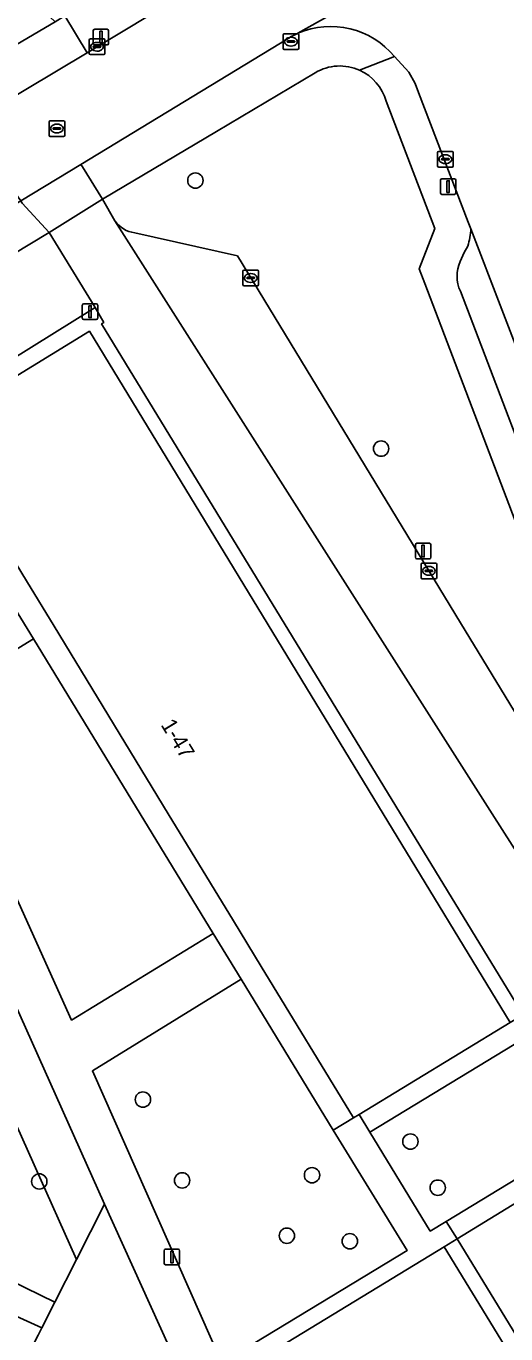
# Model space of a CAD drawing. Extents: x 159960 to 160866, y 382700 to 383354.
# Drawn here: x 160323.3 to 160353.9, y 382966.8 to 383050.3 of the extents above; entities that cross this region are included whole.
import ezdxf

# ---------------------------------------------------------------- set-up
doc = ezdxf.new("R2010")
doc.units = 0
for name, color, linetype in [('IMGEO_Boom', 7, 'Continuous'), ('IMGEO_Erf', 7, 'Continuous'), ('IMGEO_Groenvoorziening', 7, 'Continuous'), ('IMGEO_Kolk', 7, 'Continuous'), ('IMGEO_Lichtmast', 7, 'Continuous'), ('IMGEO_Pand', 7, 'Continuous'), ('IMGEO_Pand_nummerreeks', 7, 'Continuous'), ('IMGEO_Parkeervlak_open', 7, 'Continuous'), ('IMGEO_Rijbaan_lokaal_open', 7, 'Continuous'), ('IMGEO_Rioolput', 7, 'Continuous'), ('IMGEO_Voetpad_open', 7, 'Continuous')]:
    doc.layers.add(name, color=color, linetype=linetype)

msp = doc.modelspace()

# ---------------------------------------------------------------- linework, layer by layer
at = {"layer": 'IMGEO_Boom'}
for centre in [(160334.084, 383040.41), (160345.925, 383023.303), (160330.742, 382981.762), (160347.793, 382979.083), (160324.135, 382976.538), (160333.242, 382976.606), (160341.521, 382976.938), (160349.536, 382976.141), (160339.918, 382973.076), (160343.933, 382972.722)]:
    msp.add_circle(centre, 0.489, dxfattribs=at)
at = {"layer": 'IMGEO_Erf'}
msp.add_lwpolyline([(160338.283, 382990.248), (160336.511, 382993.16), (160332.352, 383000), (160325.073, 383011.971), (160323.309, 383014.872), (160317.351, 383024.674), (160327.335, 383030.788), (160346.052, 383000), (160354.153, 382986.675), (160354.977, 382987.18), (160328.108, 383031.263), (160328.241, 383031.36), (160327.687, 383032.3), (160315.507, 383024.71), (160316.015, 383023.874), (160321.983, 383014.084), (160323.762, 383011.165), (160330.567, 383000), (160335.219, 382992.368), (160336.996, 382989.452), (160342.867, 382979.821), (160344.157, 382980.593)], close=True, dxfattribs=at)
msp.add_lwpolyline([(160377.609, 382928.902), (160350.766, 382972.869), (160349.953, 382972.37), (160376.799, 382928.407)], dxfattribs=at)
at = {"layer": 'IMGEO_Groenvoorziening'}
for points in [[(160341.728, 383047.288), (160335.442, 383043.546), (160328.163, 383039.213), (160328.956, 383037.843)], [(160350.986, 383027.855), (160348.704, 383033.84), (160348.346, 383034.778), (160349.347, 383037.342), (160346.241, 383045.476)], [(160316.015, 383023.874), (160315.507, 383024.71), (160327.687, 383032.3), (160324.759, 383037.085), (160315.53, 383031.527)], [(160330.218, 383037.075), (160336.761, 383035.598), (160350.986, 383012.188), (160358.396, 383000), (160363.112, 382992.243), (160362.536, 382990.002), (160358.735, 382991.005), (160363.982, 382982.064)], [(160367.124, 382980.721), (160368.513, 382981.603), (160361.585, 383000), (160361.047, 383001.415), (160350.986, 383027.855)], [(160312.984, 383001.767), (160326.499, 382971.558), (160328.285, 382975.093), (160317.112, 383000.067)], [(160352.331, 382917.287), (160348.225, 382919.407), (160339.351, 382923.988), (160327.271, 382930.315), (160324.735, 382931.639), (160310.176, 382939.24), (160309.738, 382939.468), (160324.059, 382966.726), (160324.298, 382967.199), (160317.027, 382970.5)]]:
    msp.add_lwpolyline(points, dxfattribs=at)
for points in [[(160330.567, 383000), (160323.762, 383011.165), (160317.074, 383007.055), (160326.198, 382986.837), (160335.219, 382992.368)], [(160312.984, 383001.767), (160312.699, 383001.659), (160310.309, 383000.605), (160310.574, 383000), (160321.333, 382975.447), (160319.46, 382971.602), (160325.126, 382968.84), (160326.499, 382971.558)], [(160342.867, 382979.821), (160336.996, 382989.452), (160327.521, 382983.59), (160335.771, 382964.957), (160347.584, 382972.132)], [(160350.081, 382973.991), (160357.379, 382978.431), (160356.163, 382980.43), (160357.034, 382980.96), (160354.404, 382985.283), (160345.212, 382979.69), (160349.058, 382973.368)]]:
    msp.add_lwpolyline(points, close=True, dxfattribs=at)
for centre, radius, start, end in [((160343.295, 383044.661), 3.059, 65.61805, 120.81337), ((160343.297, 383044.666), 3.053, 15.37638, 65.6104), ((160330.423, 383038.833), 1.769, 214.00285, 263.35129)]:
    msp.add_arc(centre, radius, start, end, dxfattribs=at)
at = {"layer": 'IMGEO_Kolk'}
for p, q in [((160339.678, 383048.847), (160339.678, 383049.699)), ((160339.753, 383049.773), (160340.605, 383049.773)), ((160340.679, 383049.699), (160340.679, 383048.847)), ((160327.315, 383048.52), (160327.315, 383049.372)), ((160327.39, 383049.446), (160328.242, 383049.446)), ((160327.574, 383048.94), (160327.574, 383048.952)), ((160328.012, 383048.903), (160327.614, 383048.903)), ((160327.617, 383048.989), (160328.015, 383048.989)), ((160327.803, 383049.226), (160327.828, 383049.226)), ((160328.058, 383048.952), (160328.058, 383048.94)), ((160328.316, 383049.372), (160328.316, 383048.52)), ((160340.605, 383048.773), (160339.753, 383048.773)), ((160339.937, 383049.267), (160339.937, 383049.279)), ((160340.375, 383049.23), (160339.977, 383049.23)), ((160339.98, 383049.316), (160340.378, 383049.316)), ((160340.189, 383048.993), (160340.164, 383048.993)), ((160340.166, 383049.553), (160340.191, 383049.553)), ((160340.421, 383049.279), (160340.421, 383049.267)), ((160328.242, 383048.446), (160327.39, 383048.446)), ((160327.826, 383048.666), (160327.801, 383048.666)), ((160349.523, 383041.346), (160349.523, 383042.198)), ((160349.598, 383042.272), (160350.45, 383042.272)), ((160350.524, 383042.198), (160350.524, 383041.346)), ((160350.45, 383041.272), (160349.598, 383041.272)), ((160349.782, 383041.766), (160349.782, 383041.778)), ((160350.22, 383041.729), (160349.822, 383041.729)), ((160349.825, 383041.815), (160350.223, 383041.815)), ((160350.034, 383041.492), (160350.009, 383041.492)), ((160350.011, 383042.052), (160350.036, 383042.052)), ((160350.266, 383041.778), (160350.266, 383041.766)), ((160337.115, 383033.767), (160337.115, 383034.619)), ((160337.19, 383034.693), (160338.042, 383034.693)), ((160338.116, 383034.619), (160338.116, 383033.767)), ((160337.374, 383034.187), (160337.374, 383034.199)), ((160337.812, 383034.15), (160337.414, 383034.15)), ((160337.417, 383034.236), (160337.815, 383034.236)), ((160337.626, 383033.913), (160337.601, 383033.913)), ((160337.603, 383034.473), (160337.628, 383034.473)), ((160337.858, 383034.199), (160337.858, 383034.187)), ((160338.042, 383033.693), (160337.19, 383033.693)), ((160348.473, 383015.075), (160348.473, 383015.927)), ((160348.548, 383016.001), (160349.4, 383016.001)), ((160348.732, 383015.495), (160348.732, 383015.507)), ((160349.17, 383015.458), (160348.772, 383015.458)), ((160348.775, 383015.544), (160349.173, 383015.544)), ((160348.961, 383015.781), (160348.986, 383015.781)), ((160349.216, 383015.507), (160349.216, 383015.495)), ((160349.474, 383015.927), (160349.474, 383015.075)), ((160349.4, 383015.001), (160348.548, 383015.001)), ((160348.984, 383015.221), (160348.959, 383015.221))]:
    msp.add_line(p, q, dxfattribs=at)
for points in [[(160339.678, 383048.847), (160339.678, 383049.699)], [(160339.753, 383049.773), (160340.605, 383049.773)], [(160340.679, 383049.699), (160340.679, 383048.847)], [(160327.315, 383048.52), (160327.315, 383049.372)], [(160327.39, 383049.446), (160328.242, 383049.446)], [(160328.316, 383049.372), (160328.316, 383048.52)], [(160340.605, 383048.773), (160339.753, 383048.773)], [(160328.242, 383048.446), (160327.39, 383048.446)], [(160349.523, 383041.346), (160349.523, 383042.198)], [(160349.598, 383042.272), (160350.45, 383042.272)], [(160350.524, 383042.198), (160350.524, 383041.346)], [(160350.45, 383041.272), (160349.598, 383041.272)], [(160337.115, 383033.767), (160337.115, 383034.619)], [(160337.19, 383034.693), (160338.042, 383034.693)], [(160338.116, 383034.619), (160338.116, 383033.767)], [(160338.042, 383033.693), (160337.19, 383033.693)], [(160348.473, 383015.075), (160348.473, 383015.927)], [(160348.548, 383016.001), (160349.4, 383016.001)], [(160349.474, 383015.927), (160349.474, 383015.075)], [(160349.4, 383015.001), (160348.548, 383015.001)]]:
    msp.add_lwpolyline(points, dxfattribs=at)
for centre, radius, start, end in [((160339.755, 383049.697), 0.0765, 91.55205, 178.44795), ((160339.755, 383049.697), 0.0765, 91.55205, 178.44795), ((160340.603, 383049.697), 0.0765, 1.55205, 88.44795), ((160340.603, 383049.697), 0.0765, 1.55205, 88.44795), ((160327.392, 383049.37), 0.0765, 91.55205, 178.44795), ((160327.392, 383049.37), 0.0765, 91.55205, 178.44795), ((160327.614, 383048.949), 0.0403, 85.87752, 175.75265), ((160327.611, 383048.939), 0.0366, 178.93798, 274.71019), ((160328.015, 383048.946), 0.043, 264.86636, 352.45326), ((160328.019, 383048.951), 0.0386, 1.73085, 96.63898), ((160328.24, 383049.37), 0.0765, 1.55205, 88.44795), ((160328.24, 383049.37), 0.0765, 1.55205, 88.44795), ((160339.755, 383048.849), 0.0765, 181.55205, 268.44795), ((160339.755, 383048.849), 0.0765, 181.55205, 268.44795), ((160339.977, 383049.276), 0.0403, 85.87752, 175.75265), ((160339.974, 383049.266), 0.0366, 178.93798, 274.71019), ((160340.378, 383049.273), 0.043, 264.86636, 352.45326), ((160340.382, 383049.278), 0.0386, 1.73085, 96.63898), ((160340.603, 383048.849), 0.0765, 271.55205, 358.44795), ((160340.603, 383048.849), 0.0765, 271.55205, 358.44795), ((160327.392, 383048.522), 0.0765, 181.55205, 268.44795), ((160327.392, 383048.522), 0.0765, 181.55205, 268.44795), ((160328.24, 383048.522), 0.0765, 271.55205, 358.44795), ((160328.24, 383048.522), 0.0765, 271.55205, 358.44795), ((160349.6, 383042.196), 0.0765, 91.55205, 178.44795), ((160349.6, 383042.196), 0.0765, 91.55205, 178.44795), ((160350.448, 383042.196), 0.0765, 1.55205, 88.44795), ((160350.448, 383042.196), 0.0765, 1.55205, 88.44795), ((160349.6, 383041.348), 0.0765, 181.55205, 268.44795), ((160349.6, 383041.348), 0.0765, 181.55205, 268.44795), ((160349.822, 383041.775), 0.0403, 85.87752, 175.75265), ((160349.819, 383041.765), 0.0366, 178.93798, 274.71019), ((160350.223, 383041.772), 0.043, 264.86636, 352.45326), ((160350.227, 383041.777), 0.0386, 1.73085, 96.63898), ((160350.448, 383041.348), 0.0765, 271.55205, 358.44795), ((160350.448, 383041.348), 0.0765, 271.55205, 358.44795), ((160337.192, 383034.617), 0.0765, 91.55205, 178.44795), ((160337.192, 383034.617), 0.0765, 91.55205, 178.44795), ((160338.04, 383034.617), 0.0765, 1.55205, 88.44795), ((160338.04, 383034.617), 0.0765, 1.55205, 88.44795), ((160337.192, 383033.769), 0.0765, 181.55205, 268.44795), ((160337.192, 383033.769), 0.0765, 181.55205, 268.44795), ((160337.414, 383034.196), 0.0403, 85.87752, 175.75265), ((160337.411, 383034.186), 0.0366, 178.93798, 274.71019), ((160337.815, 383034.193), 0.043, 264.86636, 352.45326), ((160337.819, 383034.198), 0.0386, 1.73085, 96.63898), ((160338.04, 383033.769), 0.0765, 271.55205, 358.44795), ((160338.04, 383033.769), 0.0765, 271.55205, 358.44795), ((160348.55, 383015.925), 0.0765, 91.55205, 178.44795), ((160348.55, 383015.925), 0.0765, 91.55205, 178.44795), ((160348.772, 383015.504), 0.0403, 85.87752, 175.75265), ((160348.769, 383015.494), 0.0366, 178.93798, 274.71019), ((160349.173, 383015.501), 0.043, 264.86636, 352.45326), ((160349.177, 383015.506), 0.0386, 1.73085, 96.63898), ((160349.398, 383015.925), 0.0765, 1.55205, 88.44795), ((160349.398, 383015.925), 0.0765, 1.55205, 88.44795), ((160348.55, 383015.077), 0.0765, 181.55205, 268.44795), ((160348.55, 383015.077), 0.0765, 181.55205, 268.44795), ((160349.398, 383015.077), 0.0765, 271.55205, 358.44795), ((160349.398, 383015.077), 0.0765, 271.55205, 358.44795)]:
    msp.add_arc(centre, radius, start, end, dxfattribs=at)
for centre, major_axis, ratio, start_param, end_param in [((160327.802, 383048.946), (-0.387, 0.002), 0.722429, 4.712389, 7.853982), ((160327.827, 383048.946), (-0.39, 0.002), 0.717154, 1.570796, 4.712389), ((160340.165, 383049.273), (-0.387, 0.002), 0.722429, 4.712389, 7.853982), ((160340.19, 383049.273), (-0.39, 0.002), 0.717154, 1.570796, 4.712389), ((160350.01, 383041.772), (-0.387, 0.002), 0.722429, 4.712389, 7.853982), ((160350.035, 383041.772), (-0.39, 0.002), 0.717154, 1.570796, 4.712389), ((160337.602, 383034.193), (-0.387, 0.002), 0.722429, 4.712389, 7.853982), ((160337.627, 383034.193), (-0.39, 0.002), 0.717154, 1.570796, 4.712389), ((160348.96, 383015.501), (-0.387, 0.002), 0.722429, 4.712389, 7.853982), ((160348.985, 383015.501), (-0.39, 0.002), 0.717154, 1.570796, 4.712389)]:
    msp.add_ellipse(centre, major_axis=major_axis, ratio=ratio, start_param=start_param, end_param=end_param, dxfattribs=at)
at = {"layer": 'IMGEO_Lichtmast'}
for p, q in [((160327.566, 383049.164), (160327.566, 383049.964)), ((160327.566, 383049.964), (160327.566, 383049.164)), ((160327.666, 383050.064), (160328.456, 383050.064)), ((160328.456, 383050.064), (160327.666, 383050.064)), ((160328.556, 383049.964), (160328.556, 383049.164)), ((160328.556, 383049.164), (160328.556, 383049.964)), ((160328.456, 383049.064), (160327.666, 383049.064)), ((160327.666, 383049.064), (160328.456, 383049.064)), ((160349.705, 383039.624), (160349.705, 383040.424)), ((160349.705, 383040.424), (160349.705, 383039.624)), ((160349.805, 383040.524), (160350.595, 383040.524)), ((160350.595, 383040.524), (160349.805, 383040.524)), ((160350.695, 383040.424), (160350.695, 383039.624)), ((160350.695, 383039.624), (160350.695, 383040.424)), ((160350.595, 383039.524), (160349.805, 383039.524)), ((160349.805, 383039.524), (160350.595, 383039.524)), ((160326.873, 383031.644), (160326.873, 383032.444)), ((160326.873, 383032.444), (160326.873, 383031.644)), ((160326.973, 383032.544), (160327.763, 383032.544)), ((160327.763, 383032.544), (160326.973, 383032.544)), ((160327.863, 383032.444), (160327.863, 383031.644)), ((160327.863, 383031.644), (160327.863, 383032.444)), ((160327.763, 383031.544), (160326.973, 383031.544)), ((160326.973, 383031.544), (160327.763, 383031.544)), ((160348.112, 383016.366), (160348.112, 383017.166)), ((160348.112, 383017.166), (160348.112, 383016.366)), ((160348.212, 383017.266), (160349.002, 383017.266)), ((160349.002, 383017.266), (160348.212, 383017.266)), ((160349.102, 383017.166), (160349.102, 383016.366)), ((160349.102, 383016.366), (160349.102, 383017.166)), ((160349.002, 383016.266), (160348.212, 383016.266)), ((160348.212, 383016.266), (160349.002, 383016.266)), ((160332.091, 382971.321), (160332.091, 382972.121)), ((160332.091, 382972.121), (160332.091, 382971.321)), ((160332.191, 382972.221), (160332.981, 382972.221)), ((160332.981, 382972.221), (160332.191, 382972.221)), ((160333.081, 382972.121), (160333.081, 382971.321)), ((160333.081, 382971.321), (160333.081, 382972.121)), ((160332.981, 382971.221), (160332.191, 382971.221)), ((160332.191, 382971.221), (160332.981, 382971.221))]:
    msp.add_line(p, q, dxfattribs=at)
for points in [[(160327.986, 383049.939), (160328.136, 383049.939), (160328.136, 383049.189), (160327.986, 383049.189), (160327.986, 383049.939)], [(160350.125, 383040.399), (160350.275, 383040.399), (160350.275, 383039.649), (160350.125, 383039.649), (160350.125, 383040.399)], [(160327.293, 383032.419), (160327.443, 383032.419), (160327.443, 383031.669), (160327.293, 383031.669), (160327.293, 383032.419)], [(160348.532, 383017.141), (160348.682, 383017.141), (160348.682, 383016.391), (160348.532, 383016.391), (160348.532, 383017.141)], [(160332.511, 382972.096), (160332.661, 382972.096), (160332.661, 382971.346), (160332.511, 382971.346), (160332.511, 382972.096)]]:
    msp.add_lwpolyline(points, dxfattribs=at)
for centre, start, end in [((160327.666, 383049.964), 90, 180), ((160327.666, 383049.964), 90, 180), ((160328.456, 383049.964), 0, 90), ((160328.456, 383049.964), 360, 90), ((160327.666, 383049.164), 180, 270), ((160327.666, 383049.164), 180, 270), ((160328.456, 383049.164), 270, 0), ((160328.456, 383049.164), 270, 0), ((160349.805, 383040.424), 90, 180), ((160349.805, 383040.424), 90, 180), ((160350.595, 383040.424), 0, 90), ((160350.595, 383040.424), 360, 90), ((160349.805, 383039.624), 180, 270), ((160349.805, 383039.624), 180, 270), ((160350.595, 383039.624), 270, 0), ((160350.595, 383039.624), 270, 0), ((160326.973, 383032.444), 90, 180), ((160326.973, 383032.444), 90, 180), ((160327.763, 383032.444), 0, 90), ((160327.763, 383032.444), 360, 90), ((160326.973, 383031.644), 180, 270), ((160326.973, 383031.644), 180, 270), ((160327.763, 383031.644), 270, 0), ((160327.763, 383031.644), 270, 0), ((160348.212, 383017.166), 90, 180), ((160348.212, 383017.166), 90, 180), ((160349.002, 383017.166), 0, 90), ((160349.002, 383017.166), 360, 90), ((160348.212, 383016.366), 180, 270), ((160348.212, 383016.366), 180, 270), ((160349.002, 383016.366), 270, 0), ((160349.002, 383016.366), 270, 0), ((160332.191, 382972.121), 90, 180), ((160332.191, 382972.121), 90, 180), ((160332.981, 382972.121), 0, 90), ((160332.981, 382972.121), 360, 90), ((160332.191, 382971.321), 180, 270), ((160332.191, 382971.321), 180, 270), ((160332.981, 382971.321), 270, 0), ((160332.981, 382971.321), 270, 0)]:
    msp.add_arc(centre, 0.1, start, end, dxfattribs=at)
at = {"layer": 'IMGEO_Pand'}
for points in [[(160354.153, 382986.675), (160346.052, 383000), (160327.335, 383030.788), (160317.351, 383024.674), (160323.309, 383014.872), (160325.073, 383011.971), (160332.352, 383000), (160336.511, 382993.16), (160338.283, 382990.248), (160344.157, 382980.593), (160344.524, 382980.816)], [(160360.992, 382931.935), (160366.855, 382922.334), (160376.799, 382928.407), (160349.953, 382972.37), (160340.008, 382966.298), (160345.878, 382956.686), (160347.7, 382953.702), (160359.171, 382934.918)]]:
    msp.add_lwpolyline(points, close=True, dxfattribs=at)
at = {"layer": 'IMGEO_Parkeervlak_open'}
for points in [[(160328.956, 383037.843), (160353.016, 383000), (160358.735, 382991.005), (160362.536, 382990.002), (160363.112, 382992.243), (160358.396, 383000), (160350.986, 383012.188), (160336.761, 383035.598), (160330.218, 383037.075)], [(160355.596, 383027.043), (160351.648, 383037.333)], [(160351.453, 383036.228), (160351.229, 383035.817), (160350.971, 383035.248)], [(160350.986, 383033.342), (160363.686, 383000), (160368.162, 382988.249), (160368.93, 382987.351), (160369.147, 382987.178), (160370.352, 382986.491)]]:
    msp.add_lwpolyline(points, dxfattribs=at)
for centre, radius, start, end in [((160330.423, 383038.833), 1.769, 214.00285, 263.35129), ((160346.685, 383037.639), 4.972, 343.51296, 356.47108), ((160353.032, 383034.311), 2.264, 155.55469, 205.34711)]:
    msp.add_arc(centre, radius, start, end, dxfattribs=at)
at = {"layer": 'IMGEO_Rijbaan_lokaal_open'}
for points in [[(160353.698, 383067.892), (160358.04, 383071.104), (160353.872, 383076.62), (160343.659, 383087.021), (160333.639, 383097.319), (160331.452, 383095.137), (160329.265, 383092.956), (160327.078, 383090.774), (160324.891, 383088.593), (160322.704, 383086.411), (160320.517, 383084.23), (160318.33, 383082.048), (160316.143, 383079.867), (160313.956, 383077.685), (160311.769, 383075.504), (160309.582, 383073.322), (160307.395, 383071.141), (160305.208, 383068.959), (160303.025, 383066.781), (160300.321, 383064.084), (160315.353, 383049.161), (160318.121, 383046.413), (160325.142, 383050.537), (160324.477, 383051.186)], [(160354.861, 383065.364), (160349.595, 383062.176), (160344.875, 383059.245), (160337.499, 383054.792), (160327.187, 383048.566), (160319.443, 383043.946), (160322.951, 383039.108), (160326.784, 383041.444), (160340.002, 383049.482)], [(160340.624, 383049.805), (160363.348, 383062.566)], [(160362.612, 383061.814), (160363.348, 383062.566), (160340.624, 383049.805)], [(160346.773, 383048.318), (160347.688, 383047.317), (160348.098, 383046.611), (160348.32, 383046.02), (160351.486, 383037.755), (160351.648, 383037.333), (160355.596, 383027.043)], [(160363.982, 382982.064), (160358.735, 382991.005), (160353.016, 383000), (160328.956, 383037.843), (160328.163, 383039.213), (160324.759, 383037.085), (160327.687, 383032.3), (160328.241, 383031.36), (160328.108, 383031.263), (160354.977, 382987.18), (160359.126, 382980.375)], [(160358.481, 382977.554), (160355.325, 382975.667), (160350.766, 382972.869), (160377.609, 382928.902), (160381.033, 382931.054), (160385.877, 382933.973), (160386.604, 382934.424), (160385.083, 382938.344), (160381.544, 382935.915)]]:
    msp.add_lwpolyline(points, dxfattribs=at)
for centre, radius, start, end in [((160342.745, 383044.96), 5.289, 113.64326, 121.24177), ((160342.719, 383045.012), 5.231, 39.19947, 113.61109)]:
    msp.add_arc(centre, radius, start, end, dxfattribs=at)
at = {"layer": 'IMGEO_Rioolput'}
for p, q in [((160324.757, 383043.304), (160324.757, 383044.156)), ((160324.832, 383044.23), (160325.684, 383044.23)), ((160325.059, 383043.773), (160325.457, 383043.773)), ((160325.245, 383044.01), (160325.27, 383044.01)), ((160325.758, 383044.156), (160325.758, 383043.304)), ((160325.684, 383043.23), (160324.832, 383043.23)), ((160325.016, 383043.724), (160325.016, 383043.736)), ((160325.454, 383043.687), (160325.056, 383043.687)), ((160325.268, 383043.45), (160325.243, 383043.45)), ((160325.5, 383043.736), (160325.5, 383043.724))]:
    msp.add_line(p, q, dxfattribs=at)
for points in [[(160324.757, 383043.304), (160324.757, 383044.156)], [(160324.832, 383044.23), (160325.684, 383044.23)], [(160325.758, 383044.156), (160325.758, 383043.304)], [(160325.684, 383043.23), (160324.832, 383043.23)]]:
    msp.add_lwpolyline(points, dxfattribs=at)
for centre, radius, start, end in [((160324.834, 383044.154), 0.0765, 91.55205, 178.44795), ((160324.834, 383044.154), 0.0765, 91.55205, 178.44795), ((160325.056, 383043.733), 0.0403, 85.87752, 175.75265), ((160325.461, 383043.735), 0.0386, 1.73085, 96.63898), ((160325.682, 383044.154), 0.0765, 1.55205, 88.44795), ((160325.682, 383044.154), 0.0765, 1.55205, 88.44795), ((160324.834, 383043.306), 0.0765, 181.55205, 268.44795), ((160324.834, 383043.306), 0.0765, 181.55205, 268.44795), ((160325.053, 383043.723), 0.0366, 178.93798, 274.71019), ((160325.457, 383043.73), 0.043, 264.86636, 352.45326), ((160325.682, 383043.306), 0.0765, 271.55205, 358.44795), ((160325.682, 383043.306), 0.0765, 271.55205, 358.44795)]:
    msp.add_arc(centre, radius, start, end, dxfattribs=at)
for centre, major_axis, ratio, start_param, end_param in [((160325.244, 383043.73), (-0.387, 0.002), 0.722429, 4.712389, 7.853982), ((160325.269, 383043.73), (-0.39, 0.002), 0.717154, 1.570796, 4.712389)]:
    msp.add_ellipse(centre, major_axis=major_axis, ratio=ratio, start_param=start_param, end_param=end_param, dxfattribs=at)
at = {"layer": 'IMGEO_Voetpad_open'}
for points in [[(160344.875, 383059.245), (160349.595, 383062.176), (160354.861, 383065.364), (160353.698, 383067.892), (160336.135, 383057.218), (160325.761, 383050.913), (160327.187, 383048.566), (160337.499, 383054.792)], [(160327.187, 383048.566), (160325.761, 383050.913), (160325.142, 383050.537), (160318.121, 383046.413), (160319.443, 383043.946)], [(160328.163, 383039.213), (160326.881, 383041.285), (160326.784, 383041.444), (160322.951, 383039.108), (160323.041, 383038.96), (160324.759, 383037.085)]]:
    msp.add_lwpolyline(points, close=True, dxfattribs=at)
for points in [[(160340.002, 383049.482), (160326.784, 383041.444), (160326.881, 383041.285), (160328.163, 383039.213), (160335.442, 383043.546), (160341.728, 383047.288)], [(160344.558, 383047.447), (160346.773, 383048.318)], [(160351.648, 383037.333), (160351.486, 383037.755), (160348.32, 383046.02), (160348.098, 383046.611), (160347.688, 383047.317), (160346.773, 383048.318), (160344.558, 383047.447)], [(160346.241, 383045.476), (160349.347, 383037.342), (160348.346, 383034.778), (160348.704, 383033.84), (160350.986, 383027.855), (160361.047, 383001.415), (160361.585, 383000), (160368.513, 382981.603), (160372.054, 382983.802), (160371.361, 382985.658)], [(160315.53, 383031.527), (160324.759, 383037.085), (160323.041, 383038.96), (160322.951, 383039.108), (160314.042, 383033.682), (160312.427, 383032.562)], [(160350.971, 383035.248), (160351.229, 383035.817), (160351.453, 383036.228)], [(160370.352, 382986.491), (160369.147, 382987.178), (160368.93, 382987.351), (160368.162, 382988.249), (160363.686, 383000), (160350.986, 383033.342)], [(160313.953, 383006.13), (160317.074, 383007.055), (160323.762, 383011.165), (160321.983, 383014.084), (160315.562, 383010.268), (160311.246, 383019.431)], [(160346.336, 382952.885), (160344.5, 382955.893), (160340.858, 382953.797), (160336.371, 382964.153), (160338.655, 382965.467), (160340.008, 382966.298), (160349.953, 382972.37), (160350.766, 382972.869), (160350.081, 382973.991), (160349.058, 382973.368), (160345.212, 382979.69), (160344.524, 382980.816), (160344.157, 382980.593), (160342.867, 382979.821), (160347.584, 382972.132), (160335.771, 382964.957), (160327.521, 382983.59), (160336.996, 382989.452), (160335.219, 382992.368), (160326.198, 382986.837), (160317.074, 383007.055), (160313.953, 383006.13)], [(160270.263, 382977.559), (160268.268, 382982.137), (160264.871, 382980.644), (160271.091, 382965.33), (160314.265, 382984.46), (160316.003, 382983.683), (160319.505, 382975.412), (160317.027, 382970.5), (160324.298, 382967.199), (160325.126, 382968.84), (160319.46, 382971.602), (160321.333, 382975.447), (160310.574, 383000)], [(160317.112, 383000.067), (160328.285, 382975.093), (160351.891, 382922.979)], [(160359.126, 382980.375), (160354.977, 382987.18), (160354.153, 382986.675), (160344.524, 382980.816), (160345.212, 382979.69), (160354.404, 382985.283), (160357.034, 382980.96), (160356.163, 382980.43), (160357.379, 382978.431), (160350.081, 382973.991), (160350.766, 382972.869), (160355.325, 382975.667), (160358.481, 382977.554)], [(160328.285, 382975.093), (160326.499, 382971.558), (160325.126, 382968.84), (160324.298, 382967.199), (160324.059, 382966.726), (160309.738, 382939.468), (160310.176, 382939.24), (160324.735, 382931.639), (160329.229, 382940.342), (160331.771, 382939.03), (160327.271, 382930.315), (160339.351, 382923.988), (160340.645, 382926.493), (160349.518, 382921.911), (160348.225, 382919.407), (160352.331, 382917.287)], [(160351.891, 382922.979), (160328.285, 382975.093)]]:
    msp.add_lwpolyline(points, dxfattribs=at)
for centre, radius, start, end in [((160342.745, 383044.96), 5.289, 113.64326, 121.24177), ((160342.719, 383045.012), 5.231, 39.19947, 113.61109), ((160343.295, 383044.661), 3.059, 65.61805, 120.81337), ((160343.297, 383044.666), 3.053, 15.37638, 65.6104), ((160346.685, 383037.639), 4.972, 343.51296, 356.47108), ((160353.032, 383034.311), 2.264, 155.55469, 205.34711)]:
    msp.add_arc(centre, radius, start, end, dxfattribs=at)

# ---------------------------------------------------------------- texts
at = {"layer": 'IMGEO_Pand_nummerreeks'}
msp.add_text('1-47', height=1, rotation=301.30411, dxfattribs=at).set_placement((160331.851, 383005.68))

doc.saveas('drawing.dxf')
